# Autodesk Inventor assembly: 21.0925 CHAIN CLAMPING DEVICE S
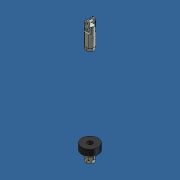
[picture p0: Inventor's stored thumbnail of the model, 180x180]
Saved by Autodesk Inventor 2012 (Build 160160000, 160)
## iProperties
Created: 2013-10
Part Number: 21.0925 CHAIN CLAMPING DEVICE S
Document SubType Name: Assembly
Designer: Admin
Author: Admin
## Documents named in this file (7)
- C:\Andys Backup Data\ANDY'S INVENTOR\INVENTOR LIBRARIES\PARTS LIBRARY\COUNTER WEIGHT SYSTEM HEAVY\21.0925 CHAIN CLAMPING DEVICE S.iam
- C:\Andys Backup Data\ANDY'S INVENTOR\INVENTOR LIBRARIES\PARTS LIBRARY\COUNTER WEIGHT SYSTEM HEAVY\SUBCOMPONENTS\21.0925 CHAIN CLAMPING DEVICE S.ipt
- C:\Andys Backup Data\ANDY'S INVENTOR\INVENTOR LIBRARIES\PARTS LIBRARY\COUNTER WEIGHT SYSTEM HEAVY\29.0308 CONNECTING LINK 08B.iam
- C:\Andys Backup Data\ANDY'S INVENTOR\INVENTOR LIBRARIES\PARTS LIBRARY\FASTENING ELEMENTS\NUTS\21.1527 M10 HEX NUT.ipt
- C:\Andys Backup Data\ANDY'S INVENTOR\INVENTOR LIBRARIES\PARTS LIBRARY\COUNTER WEIGHT SYSTEM HEAVY\SUBCOMPONENTS\21.0925 RUBBER WASHER LARGE.ipt
- C:\Andys Backup Data\ANDY'S INVENTOR\INVENTOR LIBRARIES\PARTS LIBRARY\COUNTER WEIGHT SYSTEM HEAVY\SUBCOMPONENTS\21.0925 RUBBER WASHER SMALL.ipt
- C:\Andys Backup Data\ANDY'S INVENTOR\INVENTOR LIBRARIES\PARTS LIBRARY\FASTENING ELEMENTS\WASHERS\WASHER M10 HEAVY.ipt
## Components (8 placed, 6 different names)
1. 21.0925 CHAIN CLAMPING DEVICE S:1 — Mate:1, Mate:2, Angle:1, Insert:1
2. 29.0308 CONNECTING LINK 08B:1 [sub-assembly] — Mate:1, Mate:2, Angle:1
3. 21.1527 M10 HEX NUT:1 — Insert:1, Mate:3
4. 21.1527 M10 HEX NUT:2 — Mate:3, Insert:2, Mate:4, Insert:3
5. 21.1527 M10 HEX NUT:3 — Insert:2
6. 21.0925 RUBBER WASHER LARGE:1 — Mate:4, Mate:5, Insert:5
7. 21.0925 RUBBER WASHER SMALL:1 — Mate:5, Insert:4, Insert:5
8. WASHER M10 HEAVY:1 — Insert:3, Insert:4
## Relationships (11: Mate 5, Insert 5, Angle 1)
- Mate:1: 21.0925 CHAIN CLAMPING DEVICE S:1 ↔ 29.0308 CONNECTING LINK 08B:1
- Mate:2: 21.0925 CHAIN CLAMPING DEVICE S:1 ↔ 29.0308 CONNECTING LINK 08B:1
- Angle:1: 21.0925 CHAIN CLAMPING DEVICE S:1 ↔ 29.0308 CONNECTING LINK 08B:1
- Insert:1: 21.0925 CHAIN CLAMPING DEVICE S:1 ↔ 21.1527 M10 HEX NUT:1
- Mate:3: 21.1527 M10 HEX NUT:1 ↔ 21.1527 M10 HEX NUT:2
- Insert:2: 21.1527 M10 HEX NUT:2 ↔ 21.1527 M10 HEX NUT:3
- Mate:4: 21.1527 M10 HEX NUT:2 ↔ 21.0925 RUBBER WASHER LARGE:1
- Mate:5: 21.0925 RUBBER WASHER LARGE:1 ↔ 21.0925 RUBBER WASHER SMALL:1
- Insert:3: 21.1527 M10 HEX NUT:2 ↔ WASHER M10 HEAVY:1
- Insert:4: 21.0925 RUBBER WASHER SMALL:1 ↔ WASHER M10 HEAVY:1
- Insert:5: 21.0925 RUBBER WASHER LARGE:1 ↔ 21.0925 RUBBER WASHER SMALL:1
